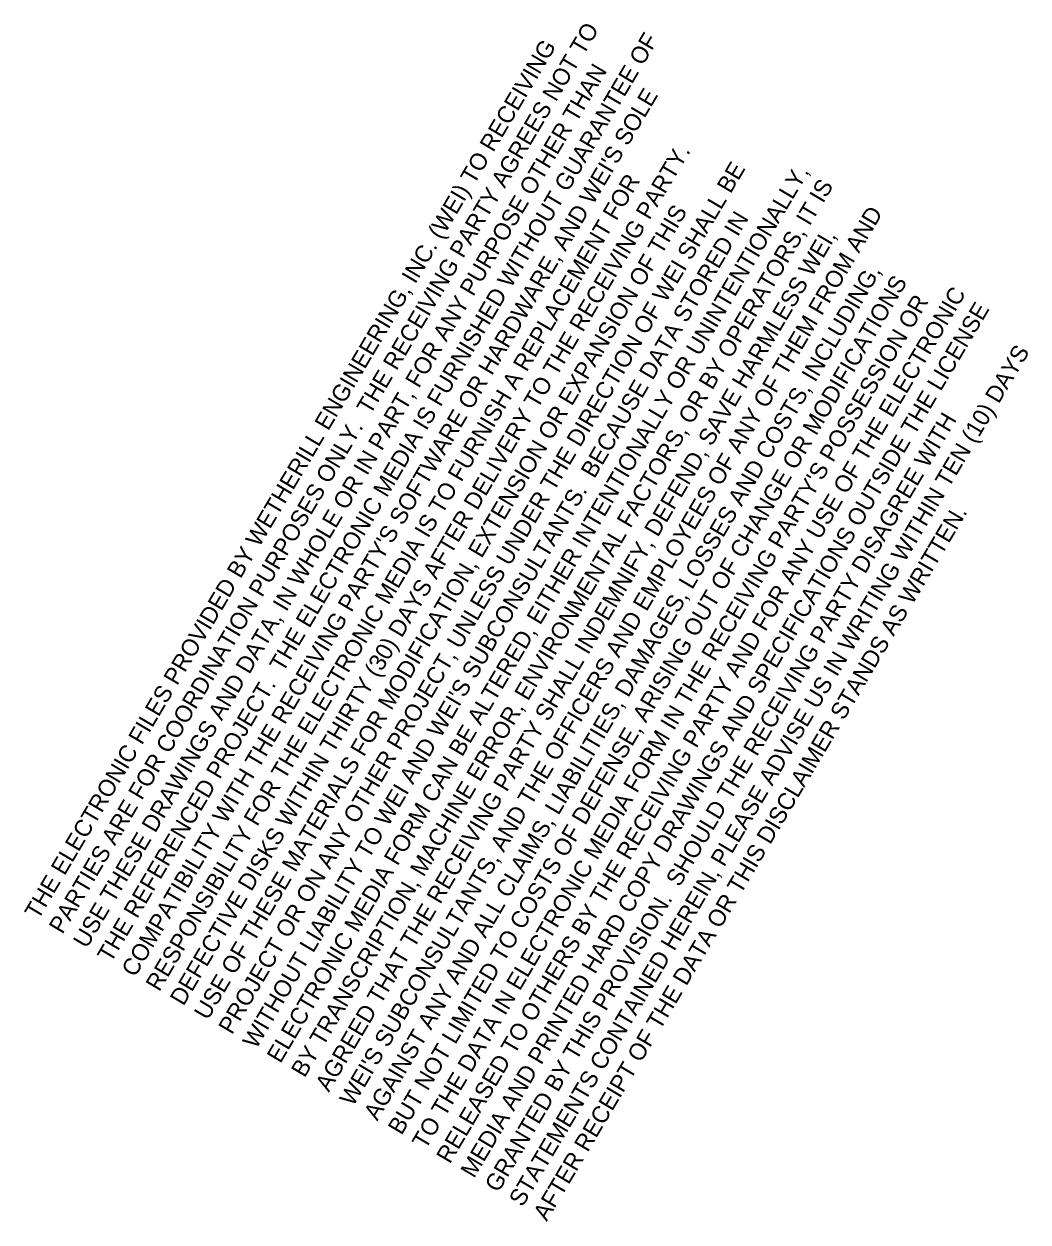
# Model space of a CAD drawing. Extents: x 2137081 to 2142019, y 404041 to 411238.
# Drawn here: x 2137081 to 2138432, y 404041 to 405653 of the extents above; entities that cross this region are included whole.
import ezdxf

# ---------------------------------------------------------------- set-up
doc = ezdxf.new("R2010")
doc.units = 0
doc.layers.add('Default', color=7, linetype='Continuous')

msp = doc.modelspace()

# ---------------------------------------------------------------- texts
at = {"layer": 'Default'}
for s, p in [('PARTIES ARE FOR COORDINATION PURPOSES ONLY.  THE RECEIVING PARTY AGREES NOT TO ', (2137132.8, 404427.1)), ('THE ELECTRONIC FILES PROVIDED BY WETHERILL ENGINEERING, INC. (WEI) TO RECEIVING ', (2137100.2, 404446.4)), ('THE REFERENCED PROJECT.  THE ELECTRONIC MEDIA IS FURNISHED WITHOUT GUARANTEE OF ', (2137198, 404388.5)), ('USE THESE DRAWINGS AND DATA, IN WHOLE OR IN PART, FOR ANY PURPOSE OTHER THAN ', (2137165.4, 404407.8)), ("COMPATIBILITY WITH THE RECEIVING PARTY'S SOFTWARE OR HARDWARE, AND WEI'S SOLE ", (2137230.5, 404369.1)), ('DEFECTIVE DISKS WITHIN THIRTY (30) DAYS AFTER DELIVERY TO THE RECEIVING PARTY.  ', (2137295.7, 404330.5)), ('PROJECT OR ON ANY OTHER PROJECT, UNLESS UNDER THE DIRECTION OF WEI SHALL BE ', (2137360.9, 404291.9)), ('RESPONSIBILITY FOR THE ELECTRONIC MEDIA IS TO FURNISH A REPLACEMENT FOR ', (2137263.1, 404349.8)), ('ELECTRONIC MEDIA FORM CAN BE ALTERED, EITHER INTENTIONALLY OR UNINTENTIONALLY, ', (2137426.1, 404253.2)), ('BY TRANSCRIPTION, MACHINE ERROR, ENVIRONMENTAL FACTORS, OR BY OPERATORS, IT IS ', (2137458.7, 404233.9)), ('USE OF THESE MATERIALS FOR MODIFICATION, EXTENSION OR EXPANSION OF THIS ', (2137328.3, 404311.2)), ("WEI'S SUBCONSULTANTS, AND THE OFFICERS AND EMPLOYEES OF ANY OF THEM FROM AND ", (2137523.9, 404195.2)), ("WITHOUT LIABILITY TO WEI AND WEI'S SUBCONSULTANTS.  BECAUSE DATA STORED IN ", (2137393.5, 404272.5)), ('AGREED THAT THE RECEIVING PARTY SHALL INDEMNIFY, DEFEND, SAVE HARMLESS WEI, ', (2137491.3, 404214.6)), ('AGAINST ANY AND ALL CLAIMS, LIABILITIES, DAMAGES, LOSSES AND COSTS, INCLUDING, ', (2137556.5, 404175.9)), ('BUT NOT LIMITED TO COSTS OF DEFENSE, ARISING OUT OF CHANGE OR MODIFICATIONS ', (2137589.1, 404156.6)), ('RELEASED TO OTHERS BY THE RECEIVING PARTY AND FOR ANY USE OF THE ELECTRONIC ', (2137654.2, 404118)), ("TO THE DATA IN ELECTRONIC MEDIA FORM IN THE RECEIVING PARTY'S POSSESSION OR ", (2137621.6, 404137.3)), ('MEDIA AND PRINTED HARD COPY DRAWINGS AND SPECIFICATIONS OUTSIDE THE LICENSE ', (2137686.8, 404098.6)), ('STATEMENTS CONTAINED HEREIN, PLEASE ADVISE US IN WRITING WITHIN TEN (10) DAYS ', (2137752, 404060)), ('GRANTED BY THIS PROVISION.  SHOULD THE RECEIVING PARTY DISAGREE WITH ', (2137719.4, 404079.3)), ('AFTER RECEIPT OF THE DATA OR THIS DISCLAIMER STANDS AS WRITTEN.', (2137784.6, 404040.7))]:
    msp.add_text(s, height=22.733, rotation=59.3391, dxfattribs=at).set_placement(p)

doc.saveas('drawing.dxf')
